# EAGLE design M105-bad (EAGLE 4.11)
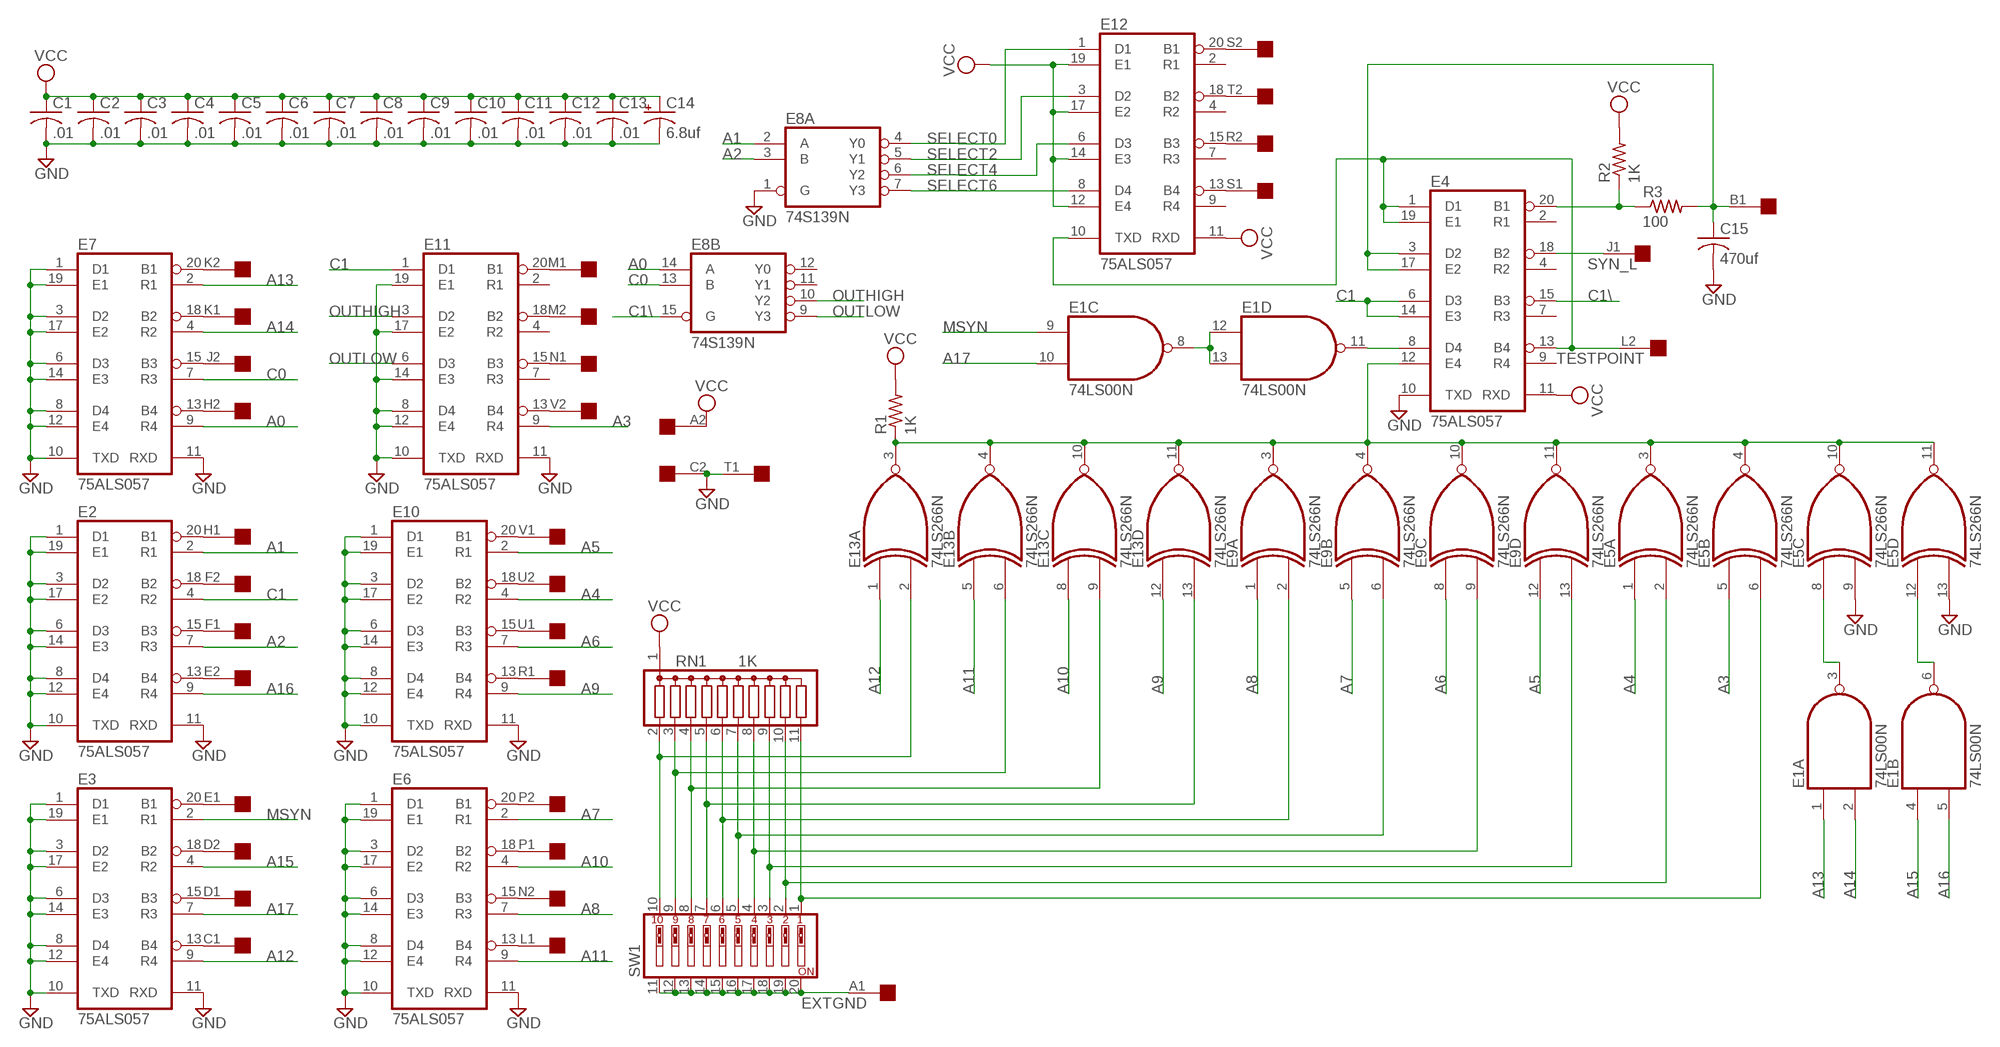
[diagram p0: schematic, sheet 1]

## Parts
C1  .01  C-US050-025X075  [C050-025X075]
C2  .01  C-US050-025X075  [C050-025X075]
C3  .01  C-US050-025X075  [C050-025X075]
C4  .01  C-US050-025X075  [C050-025X075]
C5  .01  C-US050-025X075  [C050-025X075]
C6  .01  C-US050-025X075  [C050-025X075]
C7  .01  C-US050-025X075  [C050-025X075]
C8  .01  C-US050-025X075  [C050-025X075]
C9  .01  C-US050-025X075  [C050-025X075]
C10  .01  C-US050-025X075  [C050-025X075]
C11  .01  C-US050-025X075  [C050-025X075]
C12  .01  C-US050-025X075  [C050-025X075]
C13  .01  C-US050-025X075  [C050-025X075]
C14  6.8uf  CPOL-USE15-5AXIAL  [E15-5]
C15  470uf  C-US050-025X075  [C050-025X075]
E1  74LS00N  [DIL14]
E2  75ALS057  [DIL20]
E3  75ALS057  [DIL20]
E4  75ALS057  [DIL20]
E5  74LS266N  [DIL14]
E6  75ALS057  [DIL20]
E7  75ALS057  [DIL20]
E8  74S139N  [DIL16]
E9  74LS266N  [DIL14]
E10  75ALS057  [DIL20]
E11  75ALS057  [DIL20]
E12  75ALS057  [DIL20]
E13  74LS266N  [DIL14]
R1  1K  R-US_0207/10  [0207/10]
R2  1K  R-US_0207/10  [0207/10]
R3  100  R-US_0207/10  [0207/10]
RN1  1K  G10R  [SIL11]
SW1  SW_DIP-10  [EDG-10]
U$1  SINGLE  [EDGE-CON2]

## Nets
A0: E7.9(R4) E8.14(B:A)
A1: E2.2(R1) E8.2(A:A)
A2: E2.7(R3) E8.3(A:B)
A3: E5.5(B:I0) E11.9(R4)
A4: E5.1(A:I0) E10.4(R2)
A5: E9.12(D:I0) E10.2(R1)
A6: E9.8(C:I0) E10.7(R3)
A7: E6.2(R1) E9.5(B:I0)
A8: E6.7(R3) E9.1(A:I0)
A9: E10.9(R4) E13.12(D:I0)
A10: E6.4(R2) E13.8(C:I0)
A11: E6.9(R4) E13.5(B:I0)
A12: E3.9(R4) E13.1(A:I0)
A13: E1.1(A:I0) E7.2(R1)
A14: E1.2(A:I1) E7.4(R2)
A15: E1.4(B:I0) E3.4(R2)
A16: E1.5(B:I1) E2.9(R4)
A17: E1.10(C:I1) E3.7(R3)
C0: E7.7(R3) E8.13(B:B)
C1: E2.4(R2) E4.6(D3) E4.14(E3) E11.1(D1)
C1\: E4.15(B3) E8.15(B:G)
EXTGND: SW1.11 SW1.12 SW1.13 SW1.14 SW1.15 SW1.16 SW1.17 SW1.18 SW1.19 SW1.20 U$1.A1
GND: C1.2 C2.2 C3.2 C4.2 C5.2 C6.2 C7.2 C8.2 C9.2 C10.2 C11.2 C12.2 C13.2 C14.- C15.2 E2.1(D1) E2.3(D2) E2.6(D3) E2.8(D4) E2.10(TXD) E2.11(RXD) E2.12(E4) E2.14(E3) E2.17(E2) E2.19(E1) E3.1(D1) E3.3(D2) E3.6(D3) E3.8(D4) E3.10(TXD) E3.11(RXD) E3.12(E4) E3.14(E3) E3.17(E2) E3.19(E1) E4.10(TXD) E5.9(C:I1) E5.13(D:I1) E6.1(D1) E6.3(D2) E6.6(D3) E6.8(D4) E6.10(TXD) E6.11(RXD) E6.12(E4) E6.14(E3) E6.17(E2) E6.19(E1) E7.1(D1) E7.3(D2) E7.6(D3) E7.8(D4) E7.10(TXD) E7.11(RXD) E7.12(E4) E7.14(E3) E7.17(E2) E7.19(E1) E8.1(A:G) E10.1(D1) E10.3(D2) E10.6(D3) E10.8(D4) E10.10(TXD) E10.11(RXD) E10.12(E4) E10.14(E3) E10.17(E2) E10.19(E1) E11.8(D4) E11.10(TXD) E11.11(RXD) E11.12(E4) E11.14(E3) E11.17(E2) E11.19(E1) U$1.C2 U$1.T1
MSYN: E1.9(C:I0) E3.2(R1)
N$1: E3.18(B2) U$1.D2
N$2: E3.20(B1) U$1.E1
N$3: E3.15(B3) U$1.D1
N$4: E3.13(B4) U$1.C1
N$5: E2.18(B2) U$1.F2
N$6: E2.13(B4) U$1.E2
N$7: E2.20(B1) U$1.H1
N$8: E2.15(B3) U$1.F1
N$9: E7.20(B1) U$1.K2
N$10: E7.15(B3) U$1.J2
N$11: E7.13(B4) U$1.H2
N$12: E7.18(B2) U$1.K1
N$13: E6.15(B3) U$1.N2
N$14: E6.20(B1) U$1.P2
N$15: E6.13(B4) U$1.L1
N$16: E6.18(B2) U$1.P1
N$17: E10.18(B2) U$1.U2
N$18: E11.13(B4) U$1.V2
N$19: E10.13(B4) U$1.R1
N$20: E10.15(B3) U$1.U1
N$21: E10.20(B1) U$1.V1
N$22: E4.20(B1) R2.1 R3.1
N$23: E12.20(B1) U$1.S2
N$24: E12.18(B2) U$1.T2
N$25: E12.13(B4) U$1.S1
N$26: E12.15(B3) U$1.R2
N$27: E11.18(B2) U$1.M2
N$28: E11.15(B3) U$1.N1
N$29: E1.3(A:O) E5.8(C:I0)
N$30: E1.6(B:O) E5.12(D:I0)
N$31: E1.8(C:O) E1.12(D:I0) E1.13(D:I1)
N$32: E1.11(D:O) E4.8(D4)
N$33: E5.6(B:I1) RN1.11 SW1.1
N$34: E5.2(A:I1) RN1.10 SW1.2
N$35: E9.13(D:I1) RN1.9 SW1.3
N$36: E9.9(C:I1) RN1.8 SW1.4
N$37: E9.6(B:I1) RN1.7 SW1.5
N$38: E9.2(A:I1) RN1.6 SW1.6
N$39: E13.13(D:I1) RN1.5 SW1.7
N$40: E13.9(C:I1) RN1.4 SW1.8
N$41: E13.6(B:I1) RN1.3 SW1.9
N$42: E13.2(A:I1) RN1.2 SW1.10
N$43: E4.12(E4) E5.3(A:O) E5.4(B:O) E5.10(C:O) E5.11(D:O) E9.3(A:O) E9.4(B:O) E9.10(C:O) E9.11(D:O) E13.3(A:O) E13.4(B:O) E13.10(C:O) E13.11(D:O) R1.1
N$44: C15.1 E4.3(D2) E4.17(E2) R3.2 U$1.B1
N$45: E11.20(B1) U$1.M1
OUTHIGH: E8.10(B:Y2) E11.3(D2)
OUTLOW: E8.9(B:Y3) E11.6(D3)
SELECT0: E8.4(A:Y0) E12.1(D1)
SELECT2: E8.5(A:Y1) E12.3(D2)
SELECT4: E8.6(A:Y2) E12.6(D3)
SELECT6: E8.7(A:Y3) E12.8(D4)
SYN_L: E4.18(B2) U$1.J1
TESTPOINT: E4.1(D1) E4.13(B4) E4.19(E1) E12.10(TXD) U$1.L2
VCC: C1.1 C2.1 C3.1 C4.1 C5.1 C6.1 C7.1 C8.1 C9.1 C10.1 C11.1 C12.1 C13.1 C14.+ E4.11(RXD) E12.11(RXD) E12.12(E4) E12.14(E3) E12.17(E2) E12.19(E1) R1.2 R2.2 RN1.1 U$1.A2
Unconnected: E4.2(R1) E4.4(R2) E4.7(R3) E4.9(R4) E8.11(B:Y1) E8.12(B:Y0) E11.2(R1) E11.4(R2) E11.7(R3) E12.2(R1) E12.4(R2) E12.7(R3) E12.9(R4) U$1.B2

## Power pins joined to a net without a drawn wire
GND: E1.7(P:GND) E2.16(GND) E3.16(GND) E4.16(GND) E5.7(P:GND) E6.16(GND) E7.16(GND) E8.8(P:GND) E9.7(P:GND) E10.16(GND) E11.16(GND) E12.16(GND) E13.7(P:GND)
VCC: E1.14(P:VCC) E2.5(VCC) E3.5(VCC) E4.5(VCC) E5.14(P:VCC) E6.5(VCC) E7.5(VCC) E8.16(P:VCC) E9.14(P:VCC) E10.5(VCC) E11.5(VCC) E12.5(VCC) E13.14(P:VCC)

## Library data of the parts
C1-C13 C15 = rcl:C-US: CAPACITOR, American symbol
C14 = rcl:CPOL-US: POLARIZED CAPACITOR, American symbol
E1 = 74xx-jameco:74*00: Quad 2-input NAND gate
E2-E4 E6 E7 E10-E12 = dec-con:75ALS057: Qbus Compatible Transceiver
E5 E9 E13 = 74xx-jameco:74*266: Quadruple EXCLUSIVE-NOR (XNOR), open-collector
E8 = 74xx-jameco:74*139: Dual 2-line to 4-line DECODER/DEMULTIPLEXER
R1-R3 = rcl:R-US_: RESISTOR, American symbol
RN1 = resistor-sil:G10R: SIL RESISTOR
SW1 = special:SW_DIP-10: DIP SWITCH
U$1 = dec-con:SINGLE: Single-Height DEC board

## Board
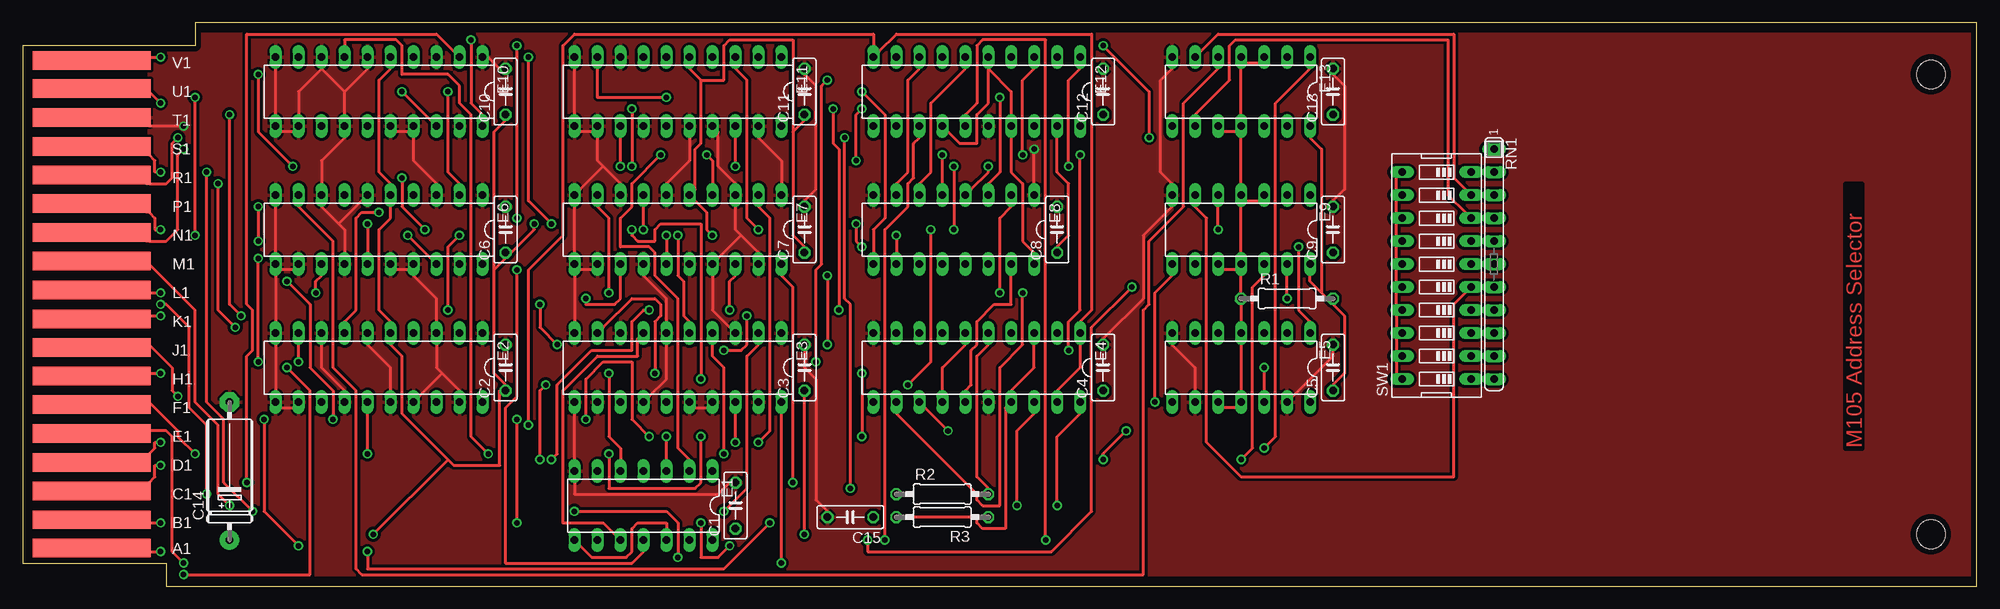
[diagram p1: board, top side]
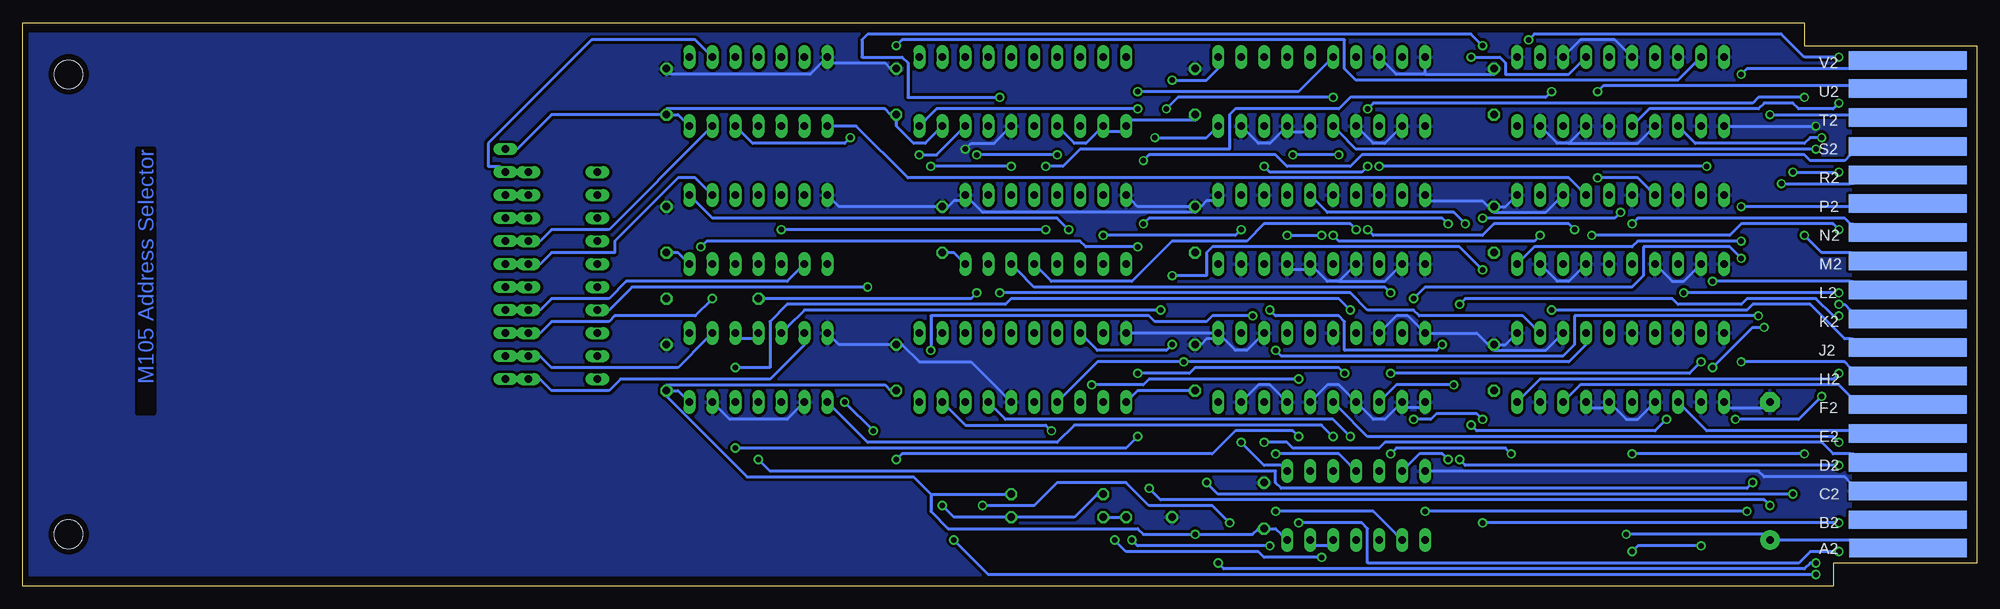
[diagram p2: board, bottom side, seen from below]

Size 215.9 x 62.23 mm. Coordinates in mm from the lower left corner, seen from the top.
Outline: 19.05,62.23 19.05,59.69 0,59.69 0,2.54 15.88,2.54 15.88,0 215.9,0 215.9,62.23 19.05,62.23
Copper layers (1*16): Top 0.035mm / dielectric 1.5mm / Bottom 0.035mm
Design rules "15mils": minimum track width 12mil, minimum drill 24mil, track to track 12mil, track to pad 10mil, pad to pad 10mil, via to via 10mil, smd to smd 10mil, copper to edge 25mil, drill to drill 10mil, minimum pad ring 10mil, minimum via ring 8mil, stop-mask expansion 0mil, vias tented up to drill 0mil, thermal gap 10mil
Holes 3.17 mm at 210.82,56.52 210.82,5.71

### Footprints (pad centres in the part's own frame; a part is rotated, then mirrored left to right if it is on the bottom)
C050-025X075 = drill 0.813 octagon: 1 -2.54,0; 2 2.54,0
E15-5 = drill 0.813 pad 2.159 round: + -7.62,0 | drill 0.813 pad 2.159 octagon: - 7.62,0
DIL14 = drill 0.813 long: 1 -7.62,-3.81; 2 -5.08,-3.81; 3 -2.54,-3.81; 4 0,-3.81; 5 2.54,-3.81; 6 5.08,-3.81; 7 7.62,-3.81; 8 7.62,3.81; 9 5.08,3.81; 10 2.54,3.81; 11 0,3.81; 12 -2.54,3.81; 13 -5.08,3.81; 14 -7.62,3.81
DIL20 = drill 0.813 long: 1 -8.89,-3.81; 2 -6.35,-3.81; 3 -3.81,-3.81; 4 -1.27,-3.81; 5 1.27,-3.81; 6 3.81,-3.81; 7 6.35,-3.81; 8 8.89,-3.81; 9 11.43,-3.81; 10 13.97,-3.81; 11 13.97,3.81; 12 11.43,3.81; 13 8.89,3.81; 14 6.35,3.81; 15 3.81,3.81; 16 1.27,3.81; 17 -1.27,3.81; 18 -3.81,3.81; 19 -6.35,3.81; 20 -8.89,3.81
DIL16 = drill 0.813 long: 1 -8.89,-3.81; 2 -6.35,-3.81; 3 -3.81,-3.81; 4 -1.27,-3.81; 5 1.27,-3.81; 6 3.81,-3.81; 7 6.35,-3.81; 8 8.89,-3.81; 9 8.89,3.81; 10 6.35,3.81; 11 3.81,3.81; 12 1.27,3.81; 13 -1.27,3.81; 14 -3.81,3.81; 15 -6.35,3.81; 16 -8.89,3.81
0207/10 = drill 0.813 octagon: 1 -5.08,0; 2 5.08,0
SIL11 = drill 0.813 long: 1 -12.7,0; 2 -10.16,0; 3 -7.62,0; 4 -5.08,0; 5 -2.54,0; 6 0,0; 7 2.54,0; 8 5.08,0; 9 7.62,0; 10 10.16,0; 11 12.7,0
EDG-10 = drill 0.813 long: 1 -11.43,-3.81; 2 -8.89,-3.81; 3 -6.35,-3.81; 4 -3.81,-3.81; 5 -1.27,-3.81; 6 1.27,-3.81; 7 3.81,-3.81; 8 6.35,-3.81; 9 8.89,-3.81; 10 11.43,-3.81; 11 11.43,3.81; 12 8.89,3.81; 13 6.35,3.81; 14 3.81,3.81; 15 1.27,3.81; 16 -1.27,3.81; 17 -3.81,3.81; 18 -6.35,3.81; 19 -8.89,3.81; 20 -11.43,3.81
EDGE-CON2 = smd 13.017 x 2.032: A1 7.633,4.207; B1 7.639,7.327; C1 7.636,10.489; D1 7.633,13.665; E1 7.642,16.84; F1 7.642,20.041; H1 7.642,23.19; J1 7.642,26.34; K1 7.642,29.515; L1 7.642,32.69; M1 7.642,35.89; N1 7.642,39.04; P1 7.642,42.24; R1 7.642,45.39; S1 7.642,48.565; T1 7.642,51.74; U1 7.642,54.966; V1 7.642,58.026 | smd 13.017 x 2.032 bottom: A2 7.614,4.207; B2 7.642,7.328; C2 7.617,10.49; D2 7.642,13.665; E2 7.642,16.84; F2 7.617,20.041; H2 7.617,23.19; J2 7.642,26.34; K2 7.642,29.515; L2 7.642,32.69; M2 7.642,35.89; N2 7.642,39.04; P2 7.642,42.24; R2 7.642,45.39; S2 7.642,48.565; T2 7.642,51.74; U2 7.642,54.966; V2 7.642,58.026

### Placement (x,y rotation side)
C1  78.74,8.89 90 top
C2  53.34,24.13 90 top
C3  86.36,24.13 90 top
C4  119.38,24.13 90 top
C5  144.78,24.13 90 top
C6  53.34,39.37 90 top
C7  86.36,39.37 90 top
C8  114.3,39.37 90 top
C9  144.78,39.37 90 top
C10  53.34,54.61 90 top
C11  86.36,54.61 90 top
C12  119.38,54.61 90 top
C13  144.78,54.61 90 top
C14  22.86,12.7 90 top
C15  91.44,7.62 180 top
E1  68.58,8.89 180 top
E2  41.91,24.13 180 top
E3  74.93,24.13 180 top
E4  107.95,24.13 180 top
E5  134.62,24.13 180 top
E6  41.91,39.37 180 top
E7  74.93,39.37 180 top
E8  102.87,39.37 180 top
E9  134.62,39.37 180 top
E10  41.91,54.61 180 top
E11  74.93,54.61 180 top
E12  107.95,54.61 180 top
E13  134.62,54.61 180 top
R1  139.7,31.75 0 top
R2  101.6,10.16 0 top
R3  101.6,7.62 180 top
RN1  162.56,35.56 270 top
SW1  156.21,34.29 90 top
U$1  0,0 0 top

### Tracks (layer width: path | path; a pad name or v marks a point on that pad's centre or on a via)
A0  (via drill 0.61)
  Top 0.305: v64.77,32.38 64.77,40.64 63.5,41.91 E7.9
  Bottom 0.305: v64.77,32.38 65.41,33.02 104.14,33.02 106.05,34.92 E8.14
A1  (via drill 0.61)
  Top 0.305: v107.95,32.38 107.95,40.64 109.22,41.91 E8.2
  Bottom 0.305: v107.95,32.38 69.22,32.38 67.31,30.48 62.23,30.48 61.6,29.84 50.17,29.84 48.9,28.57 E2.2
A2  (via drill 0.61)
  Top 0.305: v39.37,41.27 37.47,41.27 36.83,40.64 36.83,30.48 35.56,29.21 E2.7 | v54.61,40.64 v54.61,59.69 | v107.95,53.98 107.95,45.72 106.68,44.45 E8.3
  Bottom 0.305: v39.37,41.27 40.01,40.64 v54.61,40.64 | v54.61,59.69 55.88,60.96 122.56,60.96 123.19,60.33 123.19,58.42 118.75,58.42 118.11,57.78 118.11,53.98 v107.95,53.98
A3  (via drill 0.61)
  Top 0.305: v90.17,30.48 90.17,48.26 89.54,48.9 v89.54,52.7 | v71.12,53.98 63.5,53.98 63.5,57.15 E11.9
  Bottom 0.305: v90.17,30.48 129.54,30.48 131.45,28.57 E5.5 | v89.54,52.7 88.27,53.98 v71.12,53.98
A4  (via drill 0.61)
  Top 0.305: v140.97,37.47 140.97,30.48 142.24,29.21 E5.1 | v92.71,37.47 92.08,38.1 v92.08,40.01 | v58.42,40.01 55.88,42.55 v55.88,58.42
  Bottom 0.305: v140.97,37.47 140.34,38.1 99.06,38.1 98.43,37.47 v92.71,37.47 | v92.08,40.01 91.44,40.64 59.06,40.64 v58.42,40.01 | v55.88,58.42 52.71,58.42 52.07,57.78 52.07,56.52 45.09,56.52 43.82,57.78 E10.4
A5  (via drill 0.61)
  Top 0.305: v24.77,11.43 24.77,25.4 25.4,26.04 25.4,30.48 24.77,31.11 24.77,60.96 45.72,60.96 47.63,59.05 E10.2 | v134.62,13.97 135.89,15.24 135.89,33.02 137.16,34.29 E9.12
  Bottom 0.305: v24.77,11.43 25.4,10.79 76.84,10.79 77.47,11.43 77.47,12.7 133.35,12.7 v134.62,13.97
A6  (via drill 0.61)
  Top 0.305: v125.1,20.32 125.1,32.38 127,34.29 E9.8 | v121.92,17.14 119.38,14.61 v119.38,13.97 | v74.93,16.51 74.93,11.43 74.3,10.79 64.77,10.79 v64.77,14.61 | v51.44,14.61 49.53,16.51 49.53,52.07 48.26,53.34 48.26,55.24 46.99,56.52 41.91,56.52 41.91,59.69 41.28,60.33 35.56,60.33 35.56,59.69 E10.7
  Bottom 0.305: v121.92,17.14 v125.1,20.32 | v119.38,13.97 118.75,14.61 84.46,14.61 81.92,17.14 75.57,17.14 v74.93,16.51 | v64.77,14.61 64.14,15.24 52.07,15.24 v51.44,14.61
A7  (via drill 0.61)
  Top 0.305: v46.99,54.61 46.99,45.72 48.26,44.45 E6.2 | v102.87,46.35 v102.87,39.37 | v132.08,39.37 132.08,41.91 E9.5
  Bottom 0.305: v46.99,54.61 47.63,53.98 69.22,53.98 70.49,52.7 81.92,52.7 82.55,52.07 82.55,48.26 99.06,48.26 100.97,46.35 v102.87,46.35 | v102.87,39.37 v132.08,39.37
A8  (via drill 0.61)
  Top 0.305: v41.91,45.09 41.91,41.91 v44.45,39.37 | v67.31,39.37 67.31,38.73 67.95,38.1 69.85,38.1 69.85,39.37 70.49,40.01 74.93,40.01 v74.93,22.86 | v97.79,22.23 100.33,24.77 v100.33,39.37
  Bottom 0.305: v41.91,45.09 37.47,45.09 36.2,43.81 E6.7 | v44.45,39.37 45.09,40.01 53.34,40.01 54.61,38.73 66.68,38.73 v67.31,39.37 | v74.93,22.86 91.44,22.86 92.08,22.23 v97.79,22.23 | v100.33,39.37 101.6,40.64 139.7,40.64 141.61,42.55 E9.1
A9  (via drill 0.61)
  Top 0.305: v119.38,59.69 124.46,54.61 v124.46,49.53
  Bottom 0.305: v119.38,59.69 118.75,60.33 69.85,60.33 69.85,57.15 68.58,55.88 33.02,55.88 31.12,57.78 E10.9 | v124.46,49.53 125.1,48.9 135.26,48.9 136.53,50.16 E13.12
A10
  Bottom 0.305: E6.4 43.82,43.81 45.09,45.09 118.11,45.09 123.83,50.8 126.37,50.8 E13.8
A11
  Top 0.305: E6.9 30.48,41.91 34.29,38.1 34.29,24.13 36.83,21.59 36.83,1.91 37.47,1.27 123.83,1.27 123.83,30.48 124.46,31.11 124.46,38.1 128.27,41.91 128.27,53.34 132.08,57.15 E13.5
A12  (via drill 0.61)
  Top 0.305: v69.85,23.5 69.85,29.21 70.49,29.84 70.49,31.11 69.85,31.75 67.31,31.75 64.14,28.57 E3.9 | v92.71,23.5 v92.71,16.51 | v137.16,15.24 138.43,16.51 138.43,53.34 142.24,57.15 E13.1
  Bottom 0.305: v69.85,23.5 70.49,24.13 86.36,24.13 87,23.5 v92.71,23.5 | v92.71,16.51 93.98,15.24 v137.16,15.24
A13  (via drill 0.61)
  Top 0.305: v81.28,15.88 82.55,17.14 82.55,40.64 81.28,41.91 E7.2
  Bottom 0.305: v81.28,15.88 78.74,13.34 76.84,13.34 E1.1
A14  (via drill 0.61)
  Top 0.305: v70.49,47.62 67.31,44.45 67.31,41.91 66.04,40.64 66.04,37.47 69.22,37.47 69.85,36.83 69.85,34.29 72.39,31.75 72.39,15.24 73.66,13.97 E1.2 | v75.57,47.62 76.2,46.99 76.2,44.45 E7.4
  Bottom 0.305: v70.49,47.62 v75.57,47.62
A15  (via drill 0.61)
  Top 0.305: v77.47,14.61 77.47,24.13 76.2,25.4 76.2,26.67 E3.4
  Bottom 0.305: v77.47,14.61 70.49,14.61 69.22,13.34 E1.4
A16  (via drill 0.61)
  Top 0.305: v30.48,24.77 30.48,26.67 E2.9 | v64.77,23.5 64.77,16.51 66.04,15.24 66.04,13.97 E1.5
  Bottom 0.305: v30.48,24.77 31.75,23.5 v64.77,23.5
A17
  Top 0.305: E1.10 65.41,5.71 64.14,6.99 59.69,6.99 59.69,21.59 63.5,25.4 67.95,25.4 67.95,27.3 E3.7
C0  (via drill 0.61)
  Top 0.305: v68.58,39.37 68.58,41.91 E7.7
  Bottom 0.305: v68.58,39.37 69.22,40.01 78.74,40.01 80.65,38.1 88.9,38.1 93.35,33.66 102.24,33.66 103.51,34.92 E8.13
C1  (via drill 0.61)
  Top 0.305: E4.6 104.14,26.67 101.6,24.13 101.6,21.59 E4.14 | v88.9,55.88 88.27,55.24 88.27,35.56 87.63,34.92 v87.63,24.77
  Bottom 0.305: E2.4 43.18,26.67 45.09,24.77 v87.63,24.77 97.16,24.77 100.97,20.95 E4.14 | v88.9,55.88 85.09,55.88 83.82,57.15 E11.1
C1\
  Top 0.305: E4.15 104.14,21.59 104.78,22.23 104.78,26.04 105.41,26.67 105.41,29.21 107.32,31.11 109.22,31.11 109.22,34.29 E8.15
EXTGND  (via drill 0.61)
  Top 0.305: SW1.20 151.77,23.5 151.77,24.77 SW1.19 151.77,26.04 151.77,27.3 SW1.18 151.77,28.57 151.77,29.84 SW1.17 151.77,31.11 151.77,32.38 SW1.16 151.77,33.66 151.77,34.92 SW1.15 151.77,36.2 151.77,37.47 SW1.14 151.77,38.73 151.77,40.01 SW1.13 151.77,41.27 151.77,42.55 SW1.12 151.77,43.81 151.77,45.09 SW1.11 | v122.56,33.02 118.11,28.57 118.11,8.26 113.67,3.81 93.35,3.81 v93.35,5.08 | v78.11,4.45 76.84,3.17 74.93,3.17 v74.93,6.99 | v15.24,3.81 13.97,3.81 U$1.A1
  Bottom 0.305: v122.56,33.02 148.59,33.02 151.13,30.48 SW1.17 | v93.35,5.08 92.71,4.45 v78.11,4.45 | v74.93,6.99 67.95,6.99 67.31,6.35 67.31,2.54 19.69,2.54 18.42,3.81 v15.24,3.81
GND  (via drill 0.61)
  Top 0.305: E2.12 29.85,19.68 28.58,19.68 E2.11 27.94,21.59 27.94,26.67 E2.10 27.94,29.21 27.94,34.29 E6.11 | E10.10 27.94,57.15 27.94,52.07 E10.11 28.58,50.16 29.85,50.16 E10.12 30.48,52.07 30.48,54.61 33.02,57.15 | 33.02,57.15 E10.8 33.02,57.15 | E6.11 28.58,34.92 29.85,34.92 E6.12 | E6.10 27.94,41.91 27.94,36.83 E6.11 | 34.93,40.01 35.56,39.37 35.56,36.83 E6.14 | 34.93,40.01 33.02,41.91 E6.8 33.02,44.45 33.02,46.99 35.56,49.53 E10.14 35.56,52.07 35.56,54.61 | 34.93,40.01 37.47,42.55 E6.6 | 35.56,54.61 38.1,57.15 E10.6 | 35.56,54.61 33.02,57.15 | v17.78,50.8 13.97,50.8 U$1.T1 | E5.13 140.34,20.95 144.78,25.4 144.78,26.04 C5.2 | E5.7 127,26.67 129.54,24.13 129.54,21.59 E5.9 | v111.76,48.26 111.76,44.45 E8.1 | C9.2 144.78,42.55 146.05,43.81 146.05,55.24 144.78,56.52 C13.2 | E13.7 127,57.15 125.73,55.88 125.73,45.72 127,44.45 E9.7 127,41.91 123.83,38.73 123.83,31.75 119.38,27.3 C4.2 | C10.2 52.71,57.15 51.44,58.42 E10.1 | 64.14,46.35 63.5,46.99 63.5,49.53 E11.12 62.87,50.16 61.6,50.16 E11.11 60.96,52.07 60.96,57.15 E11.10 | 64.14,46.35 66.04,44.45 E7.8 | E2.14 35.56,21.59 33.02,24.13 33.02,26.67 E2.8 | E2.6 38.1,26.67 40.64,24.13 40.64,21.59 E2.16 | E6.16 41.28,34.92 42.55,34.92 E6.17 43.18,34.29 45.72,31.75 45.72,29.21 E2.3 45.72,26.67 45.72,24.13 46.36,23.5 | 46.36,23.5 48.26,21.59 E2.19 | 46.36,23.5 43.82,20.95 E2.17 | E6.3 45.72,44.45 43.18,46.99 43.18,49.53 E10.17 42.55,50.16 41.28,50.16 E10.16 | E3.10 60.96,29.21 60.96,34.29 E7.11 | E7.12 62.87,34.92 61.6,34.92 E7.11 | E7.11 60.96,36.83 60.96,41.91 E7.10 61.6,43.81 64.14,46.35 | C15.2 88.9,8.26 87.63,9.53 87.63,22.86 86.36,24.13 86.36,26.04 C3.2
  Top 0.305: E11.19 81.28,49.53 83.82,46.99 83.82,44.45 E7.1 | C11.2 86.36,56.52 87.63,55.24 87.63,43.81 86.36,42.55 C7.2 | E3.3 78.11,28.57 76.2,30.48 76.2,34.29 E7.17 76.84,36.2 79.38,38.73 | E7.6 71.12,44.45 73.66,46.99 73.66,49.53 E11.16 | E11.17 76.84,50.16 76.84,46.35 78.74,44.45 E7.3 78.74,41.91 78.74,39.37 79.38,38.73 | 79.38,38.73 81.28,36.83 E7.19 | E3.11 60.96,19.05 60.96,13.97 E1.7 60.96,11.43 60.96,10.16 76.84,10.16 78.11,11.43 C1.2 | E3.16 74.3,19.68 75.57,19.68 E3.17 | E3.14 69.22,20.95 71.12,22.86 71.12,26.67 E3.6 71.12,29.21 71.12,31.75 68.58,34.29 E7.14
  Bottom 0.305: C14.- 23.5,19.68 27.31,19.68 E2.11 | E6.14 34.93,34.92 33.66,33.66 32.39,33.66 31.12,34.92 E6.12 | E10.3 45.09,59.05 43.82,60.33 40.01,60.33 38.74,59.05 E10.6 | v17.78,50.8 27.31,50.8 E10.11 | E4.16 107.32,20.95 111.13,24.77 116.84,24.77 118.75,26.67 C4.2 120.02,26.67 125.73,26.67 126.37,27.3 E5.7 | E5.13 139.07,19.68 137.8,18.41 131.45,18.41 130.18,19.68 E5.9 | v111.76,48.26 111.13,48.9 108.59,48.9 107.32,50.16 E12.16 | E9.7 126.37,42.55 125.73,41.91 114.94,41.91 C8.2 113.67,41.91 113.03,42.55 112.4,42.55 E8.1 111.13,42.55 109.86,41.27 86.36,41.27 C7.2 | C12.2 120.02,57.15 120.65,57.78 126.37,57.78 E13.7 127.64,57.78 128.91,56.52 144.78,56.52 C13.2 | 60.96,56.52 53.34,56.52 C10.2 | 60.96,56.52 64.14,56.52 65.41,57.78 E11.8 | E11.14 67.95,50.16 66.68,48.9 65.41,48.9 64.14,50.16 E11.12 | 60.96,56.52 60.96,57.15 E11.10 | E2.17 42.55,19.68 41.28,19.68 E2.16 40.01,19.68 38.74,18.41 37.47,18.41 36.2,19.68 E2.14 | E6.19 47.63,34.92 46.36,33.66 45.09,33.66 43.82,34.92 E6.17 | 45.09,48.9 46.36,48.9 47.63,50.16 E10.19 | 45.09,48.9 43.82,50.16 E10.17 | E6.1 51.44,42.55 52.07,41.91 52.71,41.91 C6.2 | E2.1 51.44,27.3 52.07,26.67 52.71,26.67 C2.2 | E3.8 65.41,28.57 64.14,29.84 62.87,29.84 61.6,28.57 E3.10 60.33,27.94 55.25,27.94 53.98,26.67 C2.2 | C6.2 53.98,41.91 54.61,42.55 60.33,42.55 E7.10 | E6.3 46.36,42.55 47.63,41.27 53.34,41.27 C6.2 | E2.3 46.36,27.3 47.63,26.04 53.34,26.04 C2.2 | C3.2 85.73,26.67 85.09,27.3 84.46,27.3 E3.1 | E4.10 93.35,27.94 84.46,27.94 E3.1 | C7.2 85.73,41.91 85.09,42.55 84.46,42.55 E7.1 | E8.8 93.35,42.55 92.71,41.91 87,41.91 C7.2 | E7.17 75.57,34.92 74.3,34.92 E7.16 73.03,34.92 71.76,33.66 70.49,33.66
  Bottom 0.305: E11.16 74.3,50.16 75.57,50.16 E11.17 76.84,50.16 78.11,48.9 79.38,48.9 80.65,50.16 E11.19 | E3.1 83.19,27.3 81.92,26.04 80.65,26.04 79.38,27.3 E3.3 | E3.11 61.6,19.68 62.87,19.68 E3.12 64.14,19.68 65.41,18.41 66.68,18.41 67.95,19.68 E3.14 69.22,20.95 70.49,22.23 71.76,22.23 73.03,20.95 E3.16 | E3.19 80.65,20.95 79.38,22.23 78.11,22.23 76.84,20.95 E3.17 | U$1.C2 13.97,11.43 14.61,12.06 23.5,12.06 24.13,12.7 60.33,12.7 E1.7 | 70.49,33.66 69.22,34.92 E7.14 | 70.49,33.66 65.41,33.66 64.14,34.92 E7.12 | 45.09,48.9 37.47,48.9 36.2,50.16 E10.14
  pour Bottom (isolate 0.305): 13.97,60.96 215.9,60.96 215.9,1.27 13.97,1.27
  pour Top (isolate 0.305): 13.97,60.96 215.9,60.96 215.9,1.27 13.97,1.27
MSYN  (via drill 0.61)
  Top 0.305: v77.47,8.26 80.01,10.79 80.01,25.4 81.28,26.67 E3.2
  Bottom 0.305: v77.47,8.26 66.68,8.26 64.14,5.71 E1.9
N$1  (via drill 0.61)
  Top 0.305: v78.74,15.88 78.74,19.05 E3.18
  Bottom 0.305: v78.74,15.88 76.2,15.88 75.57,15.24 66.04,15.24 65.41,15.88 17.15,15.88 15.88,14.61 13.97,14.61 U$1.D2
N$2  (via drill 0.61)
  Top 0.305: v83.82,2.54 83.82,19.05 E3.20 | v17.78,2.54 16.51,3.81 16.51,16.51 15.88,17.14 13.97,17.14 U$1.E1
  Bottom 0.305: v83.82,2.54 83.19,1.91 19.05,1.91 18.42,2.54 v17.78,2.54
N$3  (via drill 0.61)
  Top 0.305: v15.24,15.88 14.61,15.88 14.61,15.24 13.97,14.61 U$1.D1
  Bottom 0.305: v15.24,15.88 15.88,16.51 67.31,16.51 70.49,19.68 E3.15
N$4  (via drill 0.61)
  Top 0.305: v57.79,22.23 57.15,21.59 v57.15,13.97 | v15.24,13.34 14.61,13.34 14.61,12.06 13.97,11.43 U$1.C1
  Bottom 0.305: v57.79,22.23 64.14,22.23 65.41,20.95 E3.13 | v57.15,13.97 56.52,13.34 v15.24,13.34
N$5
  Bottom 0.305: E2.18 45.09,20.95 43.82,22.23 15.24,22.23 13.97,20.95 U$1.F2
N$6
  Bottom 0.305: E2.13 32.39,19.68 29.85,17.14 13.97,17.14 U$1.E2
N$7  (via drill 0.61)
  Top 0.305: v15.24,23.5 13.97,23.5 U$1.H1
  Bottom 0.305: v15.24,23.5 15.88,22.86 48.26,22.86 50.17,20.95 E2.20
N$8  (via drill 0.61)
  Top 0.305: v38.1,14.61 38.1,19.05 E2.15 | v19.05,14.61 17.15,16.51 17.15,17.14 13.97,20.32 U$1.F1
  Bottom 0.305: v19.05,14.61 v38.1,14.61
N$9  (via drill 0.61)
  Top 0.305: v85.09,11.43 85.09,33.02 83.82,34.29 E7.20 | v20.32,10.16 20.32,17.78 18.42,19.68 18.42,28.57 15.88,31.11 v15.24,31.11
  Bottom 0.305: v85.09,11.43 83.82,10.16 v20.32,10.16 | v15.24,31.11 14.61,31.11 13.97,30.48 U$1.K2
N$10  (via drill 0.61)
  Top 0.305: v71.12,38.73 71.12,36.83 E7.15 | v48.26,38.73 46.99,37.47 v46.99,30.48
  Bottom 0.305: v71.12,38.73 70.49,38.1 48.9,38.1 v48.26,38.73 | v46.99,30.48 25.4,30.48 24.77,31.11 18.42,31.11 14.61,27.3 13.97,27.3 U$1.J2
N$11  (via drill 0.61)
  Top 0.305: v62.23,31.75 62.23,31.11 65.41,31.11 66.04,31.75 66.04,34.29 E7.13 | v26.04,24.77 v26.04,36.2
  Bottom 0.305: v62.23,31.75 60.96,33.02 38.1,33.02 36.83,34.29 36.83,37.47 27.31,37.47 v26.04,36.2 | v26.04,24.77 14.61,24.77 13.97,24.13 U$1.H2
N$12  (via drill 0.61)
  Top 0.305: v78.11,30.48 78.11,33.66 78.74,34.29 E7.18 | v59.06,26.67 57.15,28.57 v57.15,31.11 | v15.24,29.84 13.97,29.84 U$1.K1
  Bottom 0.305: v78.11,30.48 77.47,29.84 70.49,29.84 69.85,29.21 69.85,26.04 59.69,26.04 v59.06,26.67 | v57.15,31.11 56.52,31.75 33.66,31.75 33.02,31.11 26.04,31.11 25.4,31.75 17.78,31.75 15.88,29.84 v15.24,29.84
N$13  (via drill 0.61)
  Top 0.305: v38.1,40.01 38.1,36.83 E6.15
  Bottom 0.305: v38.1,40.01 37.47,40.64 14.61,40.64 13.97,40.01 U$1.N2
N$14  (via drill 0.61)
  Top 0.305: v26.04,41.91 v26.04,38.1
  Bottom 0.305: v26.04,38.1 37.47,38.1 38.1,37.47 48.9,37.47 50.17,36.2 E6.20 | v26.04,41.91 13.97,41.91 U$1.P2
N$15  (via drill 0.61)
  Top 0.305: v32.39,32.38 32.39,33.66 33.02,34.29 E6.13 | v15.24,32.38 13.97,32.38 U$1.L1
  Bottom 0.305: v15.24,32.38 v32.39,32.38
N$16  (via drill 0.61)
  Top 0.305: v42.55,38.73 45.09,36.2 E6.18 | v15.24,39.37 14.61,39.37 14.61,40.64 13.97,41.27 U$1.P1
  Bottom 0.305: v42.55,38.73 27.31,38.73 26.04,40.01 15.88,40.01 v15.24,39.37
N$17  (via drill 0.61)
  Top 0.305: v41.91,54.61 45.09,51.44 E10.18
  Bottom 0.305: v41.91,54.61 41.28,55.24 13.97,55.24 U$1.U2
N$18  (via drill 0.61)
  Top 0.305: v66.04,46.35 66.04,49.53 E11.13 | v29.85,46.35 26.04,50.16 v26.04,56.52
  Bottom 0.305: v29.85,46.35 v66.04,46.35 | v26.04,56.52 25.4,57.15 13.97,57.15 U$1.V2
N$19  (via drill 0.61)
  Top 0.305: v17.15,49.53 16.51,48.9 16.51,45.09 15.88,44.45 13.97,44.45 U$1.R1
  Bottom 0.305: v17.15,49.53 18.42,49.53 19.05,48.9 31.12,48.9 32.39,50.16 E10.13
N$20  (via drill 0.61)
  Top 0.305: v15.24,53.34 13.97,54.61 U$1.U1
  Bottom 0.305: v15.24,53.34 15.88,52.7 19.69,52.7 20.32,53.34 23.5,53.34 24.13,52.7 36.2,52.7 37.47,51.44 E10.15
N$21  (via drill 0.61)
  Top 0.305: v49.53,60.33 49.53,53.34 50.8,52.07 E10.20 | v15.24,58.42 13.97,58.42 U$1.V1
  Bottom 0.305: v49.53,60.33 48.9,60.96 21.59,60.96 19.05,58.42 v15.24,58.42
N$22  (via drill 0.61)
  Top 0.305: v114.3,8.89 114.3,16.51 116.84,19.05 E4.20
  Bottom 0.305: R2.1 97.16,10.16 99.7,7.62 106.05,7.62 R3.1 107.32,7.62 113.03,7.62 v114.3,8.89
N$23  (via drill 0.61)
  Top 0.305: v92.71,52.7 92.08,52.07 v92.08,46.99
  Bottom 0.305: v92.71,52.7 114.94,52.7 116.21,51.44 E12.20 | v92.08,46.99 91.44,47.62 77.47,47.62 76.2,46.35 69.22,46.35 67.95,47.62 19.05,47.62 18.42,46.99 14.61,46.99 13.97,47.62 U$1.S2
N$24  (via drill 0.61)
  Top 0.305: v116.84,47.62 116.84,30.48 115.57,29.21 v115.57,26.04 | v80.01,29.84 80.01,26.67 79.38,26.04 v77.47,26.04 | v24.13,29.84 22.86,31.11 v22.86,52.07
  Bottom 0.305: v116.84,47.62 114.94,47.62 112.4,50.16 E12.18 | v115.57,26.04 115.57,29.84 91.44,29.84 90.81,29.21 85.09,29.21 84.46,29.84 v80.01,29.84 | v77.47,26.04 76.84,25.4 45.72,25.4 44.45,26.67 44.45,29.84 v24.13,29.84 | v22.86,52.07 13.97,52.07 U$1.T2
N$25  (via drill 0.61)
  Top 0.305: v95.25,5.08 95.25,39.37 97.79,41.91 97.79,44.45 98.43,45.09 98.43,48.9 99.06,49.53 E12.13 | v72.39,3.17 72.39,6.99 71.12,8.26 v60.96,8.26 | v25.4,8.26 22.23,11.43 22.23,18.41 20.32,20.32 v20.32,45.72 | v15.24,45.72 14.61,45.72 14.61,46.99 13.97,47.62 U$1.S1
  Bottom 0.305: v95.25,5.08 93.98,3.81 79.38,3.81 78.74,3.17 v72.39,3.17 | v25.4,8.26 v60.96,8.26 | v20.32,45.72 v15.24,45.72
N$26  (via drill 0.61)
  Top 0.305: v113.03,5.08 113.03,60.33 106.05,60.33 105.41,59.69 105.41,53.34 104.14,52.07 E12.15 | v17.78,1.27 31.75,1.27 31.75,21.59 v29.21,24.13 | v23.5,28.57 21.59,30.48 v21.59,44.45
  Bottom 0.305: v113.03,5.08 109.22,1.27 v17.78,1.27 | v29.21,24.13 24.77,28.57 v23.5,28.57 | v21.59,44.45 13.97,44.45 U$1.R2
N$27  (via drill 0.61)
  Top 0.305: v78.74,46.35 78.74,49.53 E11.18 | v67.31,52.7 v67.31,46.35 | v19.05,38.73 v19.05,53.98
  Bottom 0.305: v78.74,46.35 78.11,45.72 67.95,45.72 v67.31,46.35 | v67.31,52.7 66.68,53.34 24.77,53.34 24.13,53.98 v19.05,53.98 | v19.05,38.73 17.15,36.83 13.97,36.83 U$1.M2
N$28  (via drill 0.61)
  Top 0.305: v17.78,48.26 17.15,47.62 17.15,39.37 15.88,38.1 13.97,38.1 U$1.N1
  Bottom 0.305: v17.78,48.26 68.58,48.26 70.49,50.16 E11.15
N$29  (via drill 0.61)
  Top 0.305: v71.12,16.51 71.12,13.97 E1.3
  Bottom 0.305: v71.12,16.51 72.39,17.78 99.7,17.78 101.6,15.88 122.56,15.88 126.37,19.68 E5.8
N$30  (via drill 0.61)
  Top 0.305: v58.42,13.97 59.06,14.61 59.06,22.23 62.87,26.04 67.31,26.04 67.31,29.21 68.58,30.48 v69.22,30.48 | v137.16,24.13 137.16,21.59 E5.12
  Bottom 0.305: v58.42,13.97 59.06,14.61 61.6,14.61 62.87,13.34 E1.6 | v69.22,30.48 70.49,31.75 106.68,31.75 107.32,31.11 131.45,31.11 133.35,29.21 133.35,24.13 v137.16,24.13
N$31
  Top 0.305: E1.8 61.6,4.45 62.87,3.17 66.68,3.17 67.31,3.81 67.31,6.35 67.95,6.99 71.12,6.99 71.12,6.35 E1.12
  Bottom 0.305: E1.13 73.03,4.45 71.76,4.45 E1.12
N$32  (via drill 0.61)
  Top 0.305: v54.61,34.92 54.61,20.95 53.34,19.68 53.34,2.54 67.31,2.54 68.58,3.81 E1.11 | v88.9,34.29 v88.9,26.67
  Bottom 0.305: v54.61,34.92 57.15,37.47 84.46,37.47 85.09,36.83 85.09,34.29 v88.9,34.29 | v88.9,26.67 89.54,26.04 97.16,26.04 98.43,27.3 E4.8
N$33
  Top 0.305: SW1.1 161.29,22.86 RN1.11
  Bottom 0.305: E5.6 129.54,26.67 133.35,22.86 149.86,22.86 151.13,21.59 157.48,21.59 158.75,22.86 SW1.1
N$34
  Top 0.305: SW1.2 161.29,25.4 RN1.10
  Bottom 0.305: E5.2 140.34,27.3 143.51,24.13 157.48,24.13 158.75,25.4 SW1.2
N$35  (via drill 0.61)
  Top 0.305: SW1.3 161.29,27.94 RN1.9 | v139.7,31.75 139.7,34.29 E9.13
  Bottom 0.305: v139.7,31.75 141.61,29.84 150.5,29.84 151.13,29.21 157.48,29.21 158.75,27.94 SW1.3
N$36
  Top 0.305: SW1.4 161.29,30.48 RN1.8
  Bottom 0.305: E9.9 130.18,34.92 131.45,33.66 149.23,33.66 151.13,31.75 157.48,31.75 158.75,30.48 SW1.4
N$37
  Top 0.305: RN1.7 161.29,33.02 SW1.5 159.39,32.38 158.12,31.11 158.12,12.06 134.62,12.06 130.81,15.88 130.81,40.64 129.54,41.91 E9.6
N$38
  Top 0.305: SW1.6 161.29,35.56 RN1.6
  Bottom 0.305: E9.2 140.34,43.81 141.61,45.09 143.51,45.09 150.5,38.1 150.5,36.83 157.48,36.83 158.75,35.56 SW1.6
N$39
  Top 0.305: SW1.7 161.29,38.1 RN1.5
  Bottom 0.305: E13.13 140.34,50.16 151.13,39.37 157.48,39.37 158.75,38.1 SW1.7
N$40
  Top 0.305: RN1.4 161.29,40.64 SW1.8 159.39,41.27 157.48,43.18 157.48,60.33 133.99,60.33 133.35,59.69 133.35,55.88 129.54,52.07 E13.9
N$41
  Top 0.305: RN1.3 161.29,43.18 SW1.9 159.39,43.81 158.12,45.09 158.12,60.96 132.08,60.96 130.18,59.05 E13.6
N$42
  Top 0.305: SW1.10 161.29,45.72 RN1.2
  Bottom 0.305: E13.2 140.34,59.05 141.61,60.33 153.04,60.33 164.47,48.9 164.47,46.35 163.2,46.35 RN1.2
N$43  (via drill 0.61)
  Top 0.305: E5.10 132.72,19.68 133.99,19.68 E5.11 134.62,21.59 134.62,26.67 E5.4 134.62,29.21 134.62,31.11 R1.1 134.62,32.38 134.62,34.29 E9.11 | E13.3 136.53,57.78 135.26,57.78 E13.4 134.62,57.15 134.62,52.07 E13.11 | E13.10 132.72,50.16 133.99,50.16 E13.11 | E9.4 135.26,42.55 136.53,42.55 E9.3 | E9.10 132.72,34.92 133.99,34.92 E9.11 | v110.49,32.38 110.49,26.67 107.95,24.13 107.95,8.89 106.05,8.89 105.41,9.53 105.41,10.16 96.52,19.05 E4.12 | E9.4 134.62,41.91 134.62,36.83 E9.11 | E13.11 134.62,49.53 134.62,44.45 E9.4
  Bottom 0.305: E5.4 135.26,27.3 136.53,27.3 E5.3 | v110.49,32.38 111.13,31.75 133.99,31.75 R1.1
N$44  (via drill 0.61)
  Top 0.305: E4.3 111.76,26.67 111.76,24.13 109.22,21.59 E4.17 108.59,19.68 108.59,6.35 106.05,6.35 105.41,6.99 105.41,7.62 97.16,7.62 R3.2 | v15.24,6.99 13.97,6.99 U$1.B1 | v54.61,6.99 v54.61,18.41 | v62.23,18.41 62.23,22.86 64.14,24.77 67.31,24.77 67.31,18.41 v69.22,16.51
  Bottom 0.305: C15.1 94.62,7.62 95.89,7.62 R3.2 | v15.24,6.99 v54.61,6.99 | v54.61,18.41 55.25,19.05 59.69,19.05 60.33,18.41 v62.23,18.41 | v69.22,16.51 71.12,18.41 107.32,18.41 108.59,19.68 E4.17
N$45  (via drill 0.61)
  Top 0.305: v90.81,49.53 90.81,31.75 91.44,31.11 v91.44,10.79 | v22.86,8.89 21.59,10.16 21.59,17.78 19.05,20.32 19.05,30.48 13.97,35.56 U$1.M1
  Bottom 0.305: v90.81,49.53 85.09,49.53 84.46,50.16 E11.20 | v91.44,10.79 90.17,9.53 23.5,9.53 v22.86,8.89
OUTHIGH  (via drill 0.61)
  Top 0.305: v96.52,38.73 96.52,36.83 E8.10 | v81.28,39.37 80.01,40.64 80.01,55.88 78.74,57.15 E11.3
  Bottom 0.305: v96.52,38.73 81.92,38.73 v81.28,39.37
OUTLOW  (via drill 0.61)
  Top 0.305: v92.71,54.61 95.25,52.07 95.25,40.64 93.98,39.37 93.98,36.83 E8.9
  Bottom 0.305: v92.71,54.61 74.93,54.61 71.76,57.78 E11.6
SELECT0  (via drill 0.61)
  Top 0.305: v106.68,46.35 106.68,45.72 104.78,43.81 E8.4 | v115.57,46.35 115.57,55.88 116.84,57.15 E12.1
  Bottom 0.305: v106.68,46.35 v115.57,46.35
SELECT2  (via drill 0.61)
  Top 0.305: v101.6,47.62 101.6,44.45 E8.5 | v110.49,47.62 110.49,55.88 111.76,57.15 E12.3
  Bottom 0.305: v101.6,47.62 v110.49,47.62
SELECT4
  Top 0.305: E8.6 99.06,44.45 100.33,45.72 100.33,53.34 104.14,57.15 E12.6
SELECT6
  Top 0.305: E8.7 96.52,44.45 97.79,45.72 97.79,55.88 99.06,57.15 E12.8
SYN_L  (via drill 0.61)
  Top 0.305: v109.86,8.89 109.86,17.14 111.76,19.05 E4.18 | v82.55,6.99 77.47,1.91 38.1,1.91 v38.1,3.81 | v30.48,4.45 26.67,8.26 v26.67,18.41 | v17.15,20.95 16.51,21.59 16.51,24.13 13.97,26.67 U$1.J1
  Bottom 0.305: v109.86,8.89 104.14,8.89 101.6,11.43 93.98,11.43 91.44,8.89 84.46,8.89 v82.55,6.99 | v38.1,3.81 37.47,4.45 v30.48,4.45 | v26.67,18.41 19.69,18.41 v17.15,20.95
TESTPOINT  (via drill 0.61)
  Top 0.305: v102.24,17.14 99.7,19.68 E4.13 | E4.19 114.3,21.59 116.84,24.13 116.84,26.67 E4.1 116.84,29.21 118.11,30.48 118.11,60.96 96.52,60.96 94.62,59.05 E12.10 93.98,59.69 93.98,60.96 60.96,60.96 59.69,59.69 59.69,38.73 55.88,34.92 v55.88,17.78 | v29.21,33.66 31.75,31.11 31.75,24.13 34.29,21.59 v34.29,18.41
  Bottom 0.305: v102.24,17.14 102.87,17.78 111.76,17.78 113.67,19.68 E4.19 | v29.21,33.66 13.97,33.66 U$1.L2 | v34.29,18.41 35.56,17.14 55.25,17.14 v55.88,17.78
VCC  (via drill 0.61)
  Top 0.305: E10.5 40.64,57.15 39.37,55.88 39.37,45.72 40.64,44.45 E6.5 40.64,41.91 40.64,40.64 39.37,39.37 39.37,30.48 40.64,29.21 E2.5 40.64,26.67 41.91,25.4 41.91,19.05 46.99,13.97 | 52.07,34.92 52.07,23.5 53.34,22.23 C2.1 52.71,21.59 52.71,13.34 47.63,13.34 46.99,13.97 | 52.07,34.92 53.34,36.2 C6.1 53.98,36.83 56.52,39.37 v56.52,40.01 | 52.07,34.92 52.07,50.16 53.34,51.44 C10.1 | v38.74,5.71 46.99,13.97 | v72.39,38.73 72.39,34.29 73.03,33.66 73.03,29.84 73.66,29.21 E3.5 | v76.2,38.73 75.57,39.37 75.57,41.27 74.3,42.55 E7.5 74.3,43.81 74.3,48.26 74.93,48.9 74.93,55.88 | 74.93,55.88 73.66,57.15 E11.5 | 85.09,50.16 85.09,38.73 86.36,37.47 C7.1 | 85.09,50.16 86.36,51.44 C11.1 | 106.68,57.15 109.22,54.61 109.22,52.07 E12.17 109.22,49.53 109.22,45.72 110.49,44.45 110.49,38.1 111.76,36.83 E8.16 | 106.68,57.15 E12.5 106.68,57.15 | C8.1 114.3,37.47 115.57,38.73 115.57,44.45 114.3,45.72 114.3,49.53 E12.19 | 106.68,57.15 106.68,53.34 105.41,52.07 105.41,48.9 103.51,48.9 102.24,50.16 E12.14 | 74.93,55.88 77.47,55.88 77.47,59.69 78.11,60.33 85.09,60.33 85.09,50.16 | R2.2 106.68,10.79 105.41,12.06 105.41,25.4 106.68,26.67 E4.5 | v86.36,5.71 86.36,20.95 C3.1 | 143.51,32.38 142.24,33.66 142.24,34.29 E9.14 | 143.51,32.38 144.15,31.75 R1.2 144.78,31.11 146.05,29.84 146.05,23.5 144.78,22.23 C5.1 | 143.51,32.38 143.51,48.26 142.24,49.53 E13.14
  Bottom 0.305: U$1.A2 13.97,5.08 22.23,5.08 C14.+ 23.5,5.71 v38.74,5.71 | v76.2,38.73 v72.39,38.73 | E12.14 100.97,50.16 99.7,48.9 98.43,48.9 97.16,50.16 E12.12 95.89,50.16 94.62,50.16 E12.11 93.35,51.44 86.36,51.44 C11.1 | E8.16 112.4,36.2 113.03,36.83 113.67,36.83 C8.1 | E12.19 114.94,50.16 116.21,48.9 117.48,48.9 119.38,50.8 119.38,51.44 C12.1 120.02,52.07 120.65,52.7 144.78,52.7 C13.1 | E4.11 93.35,20.95 92.71,21.59 87,21.59 C3.1 | E1.14 76.84,5.71 77.47,6.35 78.11,6.35 C1.1 79.38,6.35 80.01,5.71 v86.36,5.71 92.08,5.71 92.71,6.35 113.67,6.35 115.57,8.26 115.57,10.16 | 115.57,10.16 107.32,10.16 R2.2 | E13.14 142.88,51.44 143.51,52.07 144.15,52.07 C13.1 | RN1.1 161.29,48.26 157.48,52.07 145.42,52.07 C13.1 | E9.14 142.88,36.2 143.51,36.83 144.15,36.83 C9.1 | E5.14 142.88,20.95 143.51,21.59 144.15,21.59 C5.1 | C4.1 120.02,21.59 120.65,22.23 144.78,22.23 C5.1 | 115.57,10.16 117.48,12.06 135.89,12.06 144.78,20.95 C5.1 | v56.52,40.01 57.79,41.27 71.76,41.27 73.03,42.55 E7.5

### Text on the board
Top: M105 Address Selector
Bottom: M105 Address Selector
